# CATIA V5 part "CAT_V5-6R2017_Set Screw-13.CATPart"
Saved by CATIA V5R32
Part number: Set Screw-13
Bounding box of the stored display mesh (mm): x -5.916 to 5.916, y -5.998 to 5.998, z -1.5 to 16
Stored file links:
  D:\PROJECTS\Project 2022\CATIA V5 6R 2022\Resources\Tutorial Files\c16_catia_v5_6r2022_tut\Bench vice\CAT_V5-6R2017_Set Screw-13.CATPart
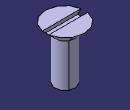
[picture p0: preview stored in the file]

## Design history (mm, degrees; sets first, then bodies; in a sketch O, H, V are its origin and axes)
Body1 (main body)
  Sketch1 on yz-plane, origin (0, 0, 0), H (0, 1, 0), V (0, 0, 1)
    point P1 (0, -1.5)
    line L1 (0, -1.5) -> (3, 0)
    point P2 (3, 0)
    line L2 (3, 0) -> (3, 13)
    line L3 (3, 13) -> (6, 16)
    point P4 (6, 16)
    line L4 (6, 16) -> (0, 16)
    point P5 (0, 16)
    line L5 (0, 16) -> (0, -1.5)
    length L2 = 13
    distance L2 L5 = 3
    distance H P1 = 1.5
    distance P4 L5 = 6
    angle L3 L5 = 45
    coincidence: P1 V, P2 H, P5 V
    vertical: L2 V, L5 V
    horizontal: L4 H
  Shaft1: profile Sketch1, axis edge of Sketch1, angle 360
  Sketch2 on yz-plane, origin (0, 0, 0), H (0, 1, 0), V (0, 0, 1)
    line L1 (-1, 16) -> (1, 16)
    line L2 (1, 16) -> (1, 15)
    line L3 (1, 15) -> (-1, 15)
    line L4 (-1, 15) -> (-1, 16)
    reference projected line E1 (-6, 16) -> (6, 16) from edge of Shaft1
    distance V L2 = 1
    length L1 = 2
    length L2 = 1
    horizontal: L1 H, L3 H
    vertical: L2 V, L4 V
    coincidence: L1 E1
  Pocket1: profile Sketch2, direction (-1, 0, 0), length 16, mirrored extent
